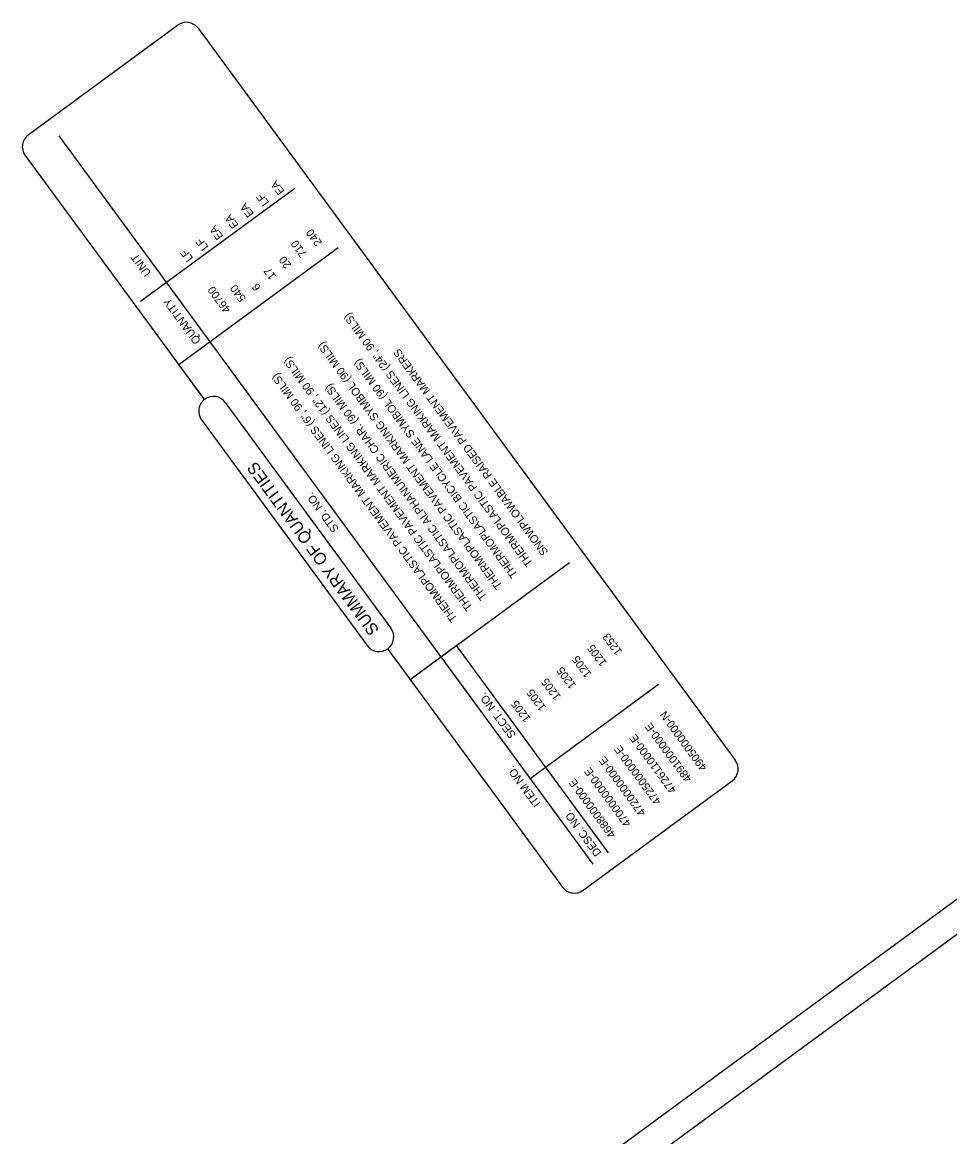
# Model space of a CAD drawing. Extents: x 719153 to 721402, y 581205 to 583188.
# Drawn here: x 719592 to 720080, y 582601 to 583188 of the extents above; entities that cross this region are included whole.
import ezdxf

# ---------------------------------------------------------------- set-up
doc = ezdxf.new("R2010")
doc.units = 0
for name, color, linetype in [('Default', 7, 'Continuous'), ('Old_Level_1', 7, 'Continuous'), ('Old_Level_50', 7, 'Continuous'), ('Sheet Plot Border Inside CELL', 7, 'Continuous')]:
    doc.layers.add(name, color=color, linetype=linetype)

msp = doc.modelspace()

# ---------------------------------------------------------------- linework, layer by layer
at = {"layer": 'Default'}
for p, q in [((719595.14, 583128.37), (719673.68, 583186.04)), ((719684.49, 583184.39), (719967.12, 582799.47)), ((719611.19, 583127.81), (719829.98, 582829.6)), ((719593.5, 583117.56), (719687.91, 582989)), ((719735.4, 583100.19), (719654.27, 583040.67)), ((719698.79, 582987.6), (719785.94, 582868.89)), ((719686.3, 582978.42), (719773.47, 582859.74)), ((719784.26, 582857.87), (719876.19, 582732.69)), ((719859.17, 582789.89), (719926.71, 582839.44)), ((719887.01, 582731.03), (719965.47, 582788.66))]:
    msp.add_line(p, q, dxfattribs=at)
for points in [[(719686.14, 582991.42), (719674.31, 583007.54), (719758.21, 583069.1)], [(719796.11, 582841.96), (719879.81, 582903.37)], [(719812.23, 582853.79), (719820.3, 582859.71), (719900.23, 582750.76)], [(719796.11, 582841.96), (719812.23, 582853.79), (719892.16, 582744.85)]]:
    msp.add_lwpolyline(points, dxfattribs=at)
for centre, start, end in [((719678.27, 583179.81), 36.36669, 126.36669), ((719599.72, 583122.14), 126.36669, 216.36669), ((719692.56, 582983.02), 126.26669, 216.26669), ((719692.56, 582983.02), 36.26669, 126.26669), ((719779.7, 582864.32), 306.26664, 36.26664), ((719779.7, 582864.32), 216.26664, 306.26664), ((719960.89, 582794.88), 306.36664, 36.36664), ((719882.43, 582737.26), 216.36664, 306.36664)]:
    msp.add_arc(centre, 7.73, start, end, dxfattribs=at)
at = {"layer": 'Old_Level_50'}
msp.add_lwpolyline([(721009.35, 582149.27), (720410.24, 582965.86), (719878.1, 582575.44), (720477.21, 581758.85)], close=True, dxfattribs=at)
at = {"layer": 'Sheet Plot Border Inside CELL'}
msp.add_lwpolyline([(719899.07, 582572.22), (720431.46, 581846.57), (720939.41, 582219.25), (720407.02, 582944.89)], close=True, dxfattribs=at)

# ---------------------------------------------------------------- texts
at = {"layer": 'Default'}
for s, height, p in [('UNIT', 4.21, (719659.96, 583055.75)), ('QUANTITY', 4.21, (719686.11, 583020.09)), ('SUMMARY OF QUANTITIES', 6.315, (719780.03, 582867.98)), ('STD. NO.', 4.21, (719758.74, 582921.11)), ('SECT. NO.', 4.21, (719851.91, 582812.83)), ('ITEM NO.', 4.21, (719864.9, 582776.72)), ('DESC. NO.', 4.21, (719896.88, 582750.74))]:
    msp.add_text(s, height=height, rotation=126.22647, dxfattribs=at).set_placement(p)
at = {"layer": 'Old_Level_1'}
for s, p in [('EA', (719730.17, 583098.68)), ('LF', (719722.1, 583092.76)), ('EA', (719714.04, 583086.85)), ('EA', (719705.98, 583080.93)), ('EA', (719697.92, 583075.02)), ('240', (719749.91, 583071.77)), ('LF', (719690.16, 583069.33)), ('710', (719741.85, 583065.86)), ('LF', (719682.1, 583063.41)), ('20', (719733.78, 583059.94)), ('17', (719725.72, 583054.02)), ('46700', (719701.84, 583036.5)), ('540', (719709.9, 583042.42)), ('6', (719717.66, 583048.11)), ('THERMOPLASTIC PAVEMENT MARKING LINES (24", 90 MILS)', (719860.84, 582903.08)), ('THERMOPLASTIC PAVEMENT MARKING SYMBOL (90 MILS)', (719844.71, 582891.25)), ('SNOWPLOWABLE RAISED PAVEMENT MARKERS', (719868.9, 582908.99)), ('THERMOPLASTIC PAVEMENT MARKING LINES (12", 90 MILS)', (719829.18, 582879.85)), ('THERMOPLASTIC BICYCLE LANE SYMBOL (90 MILS)', (719852.78, 582897.16)), ('THERMOPLASTIC PAVEMENT MARKING LINES (6", 90 MILS)', (719821.11, 582873.93)), ('THERMOPLASTIC ALPHANUMERIC CHAR. (90 MILS)', (719836.65, 582885.33)), ('1253', (719907.77, 582856.61)), ('1205', (719899.71, 582850.69)), ('1205', (719891.65, 582844.77)), ('1205', (719883.58, 582838.86)), ('1205', (719875.52, 582832.94)), ('1205', (719867.76, 582827.25)), ('1205', (719859.7, 582821.34)), ('4905000000-N', (719952.49, 582795.65)), ('4891000000-E', (719944.43, 582789.73)), ('4726110000-E', (719936.37, 582783.82)), ('4725000000-E', (719928.31, 582777.9)), ('4720000000-E', (719920.24, 582771.99)), ('4700000000-E', (719912.49, 582766.3)), ('4688000000-E', (719904.42, 582760.38))]:
    msp.add_text(s, height=4.21, rotation=126.22647, dxfattribs=at).set_placement(p)

doc.saveas('drawing.dxf')
